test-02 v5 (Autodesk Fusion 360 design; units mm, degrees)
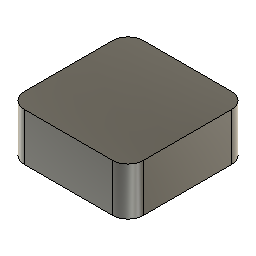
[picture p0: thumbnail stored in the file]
sketch "Sketch1" plane through (0, 0, 0) normal (0, 0, 1) x axis (1, 0, 0)
  line L1 (-50, 0) -> (0, 0)
  line L2 (-50, 50) -> (-50, 0)
  line L3 (0, 50) -> (-50, 50)
  line L4 (0, 0) -> (0, 50)
  point P1 (0, 0)
  point P2 (0, 0)
  point P3 (-50, 0)
  point P5 (0, 50)
  horizontal L1
  vertical L2
  horizontal L3
  vertical L4
  coincident P1 P2
  dimension "d1" distance P2 P3 = 50
  dimension "d2" distance P2 P5 = 50
extrude "Extrude1" new body sketch "Sketch1" along normal blind 20
fillet "Fillet1" radius 6.5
